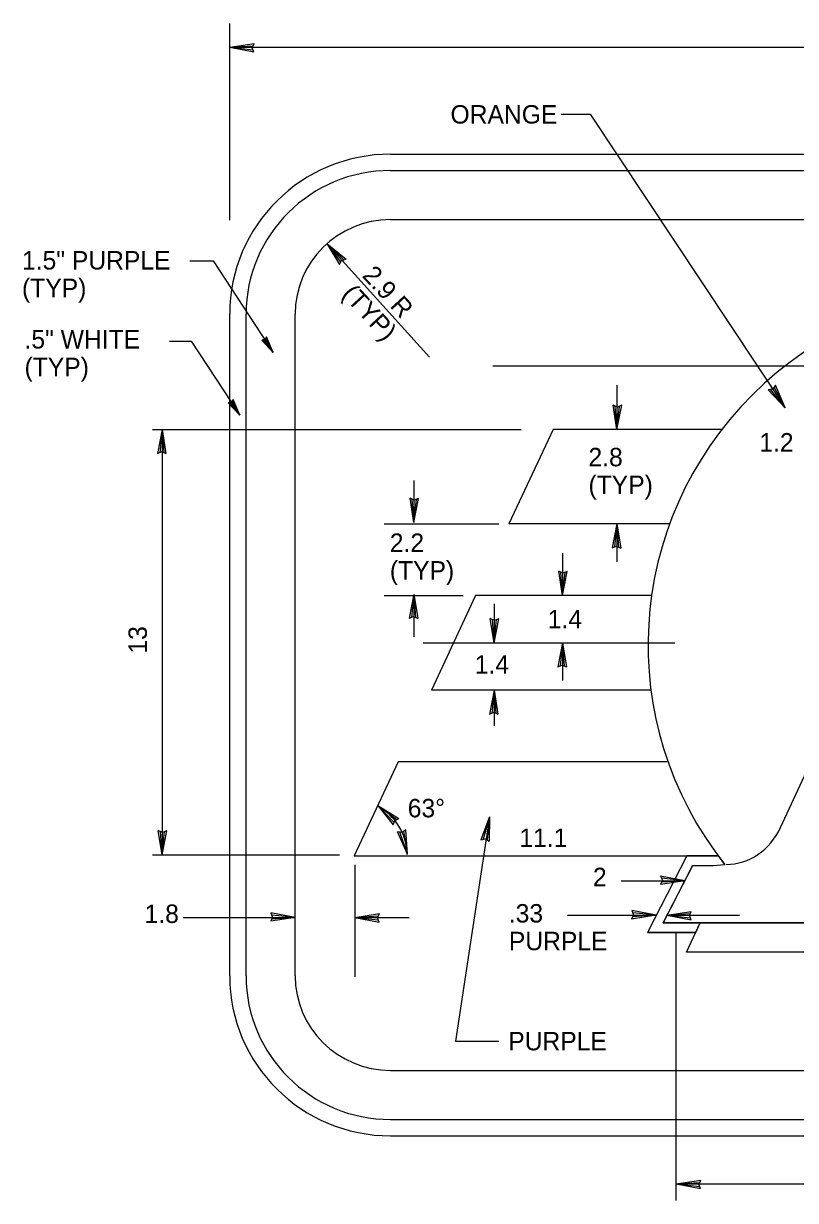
# Model space of a CAD drawing. Extents: x 10268197 to 10269179, y 2141503 to 2142677.
# Drawn here: x 10268665.92 to 10268695.42, y 2141995.31 to 2142040.27 of the extents above; entities that cross this region are included whole.
import ezdxf

# ---------------------------------------------------------------- set-up
doc = ezdxf.new("R2010")
doc.units = 0
for name, color, linetype in [('1', 7, 'Continuous'), ('Default', 7, 'Continuous'), ('TextMisc', 7, 'Continuous'), ('TextShtNo', 7, 'Continuous')]:
    doc.layers.add(name, color=color, linetype=linetype)

msp = doc.modelspace()

# ---------------------------------------------------------------- linework, layer by layer
at = {"layer": '1'}
for p, q in [((10268677.514, 2142031.863), (10268681.429, 2142027.519)), ((10268683.723, 2142009.967), (10268682.426, 2142001.389)), ((10268691.605, 2142005.546), (10268689.757, 2142005.546)), ((10268682.426, 2142001.389), (10268684.078, 2142001.389))]:
    msp.add_line(p, q, dxfattribs=at)
msp.add_ellipse((10268678.4, 2142008.499), major_axis=(-2.172, 0), ratio=0.990479, start_param=3.156002, end_param=4.207879, dxfattribs=at)
at = {"layer": 'Default'}
for p, q in [((10268673.796, 2142032.755), (10268673.796, 2142040.27)), ((10268673.796, 2142039.361), (10268674.728, 2142039.507)), ((10268673.796, 2142039.361), (10268674.689, 2142039.423)), ((10268673.796, 2142039.361), (10268722.546, 2142039.361)), ((10268673.796, 2142039.361), (10268674.723, 2142039.183)), ((10268673.796, 2142039.361), (10268674.687, 2142039.269)), ((10268674.654, 2142039.346), (10268674.728, 2142039.507)), ((10268674.723, 2142039.183), (10268674.654, 2142039.346)), ((10268686.467, 2142036.81), (10268687.571, 2142036.81)), ((10268687.571, 2142036.81), (10268695.023, 2142025.595)), ((10268679.942, 2142032.78), (10268716.4, 2142032.78)), ((10268677.514, 2142031.863), (10268678.246, 2142031.271)), ((10268677.514, 2142031.863), (10268677.997, 2142031.06)), ((10268677.514, 2142031.863), (10268678.038, 2142031.142)), ((10268677.514, 2142031.863), (10268678.155, 2142031.244)), ((10268672.274, 2142031.203), (10268673.161, 2142031.203)), ((10268673.161, 2142031.203), (10268675.463, 2142027.704)), ((10268677.997, 2142031.06), (10268678.074, 2142031.218)), ((10268678.074, 2142031.218), (10268678.246, 2142031.271)), ((10268676.296, 2142003.891), (10268676.296, 2142029.168)), ((10268671.5, 2142028.133), (10268672.326, 2142028.133)), ((10268672.326, 2142028.133), (10268674.183, 2142025.311)), ((10268675.14, 2142028.196), (10268675.019, 2142028.175)), ((10268675.463, 2142027.704), (10268675.019, 2142028.175)), ((10268675.463, 2142027.704), (10268675.082, 2142028.186)), ((10268675.207, 2142028.298), (10268675.14, 2142028.196)), ((10268675.463, 2142027.704), (10268675.171, 2142028.245)), ((10268675.463, 2142027.704), (10268675.207, 2142028.298)), ((10268683.847, 2142027.195), (10268700.38, 2142027.195)), ((10268694.99, 2142027.195), (10268699.515, 2142027.195)), ((10268688.595, 2142026.455), (10268688.595, 2142024.767)), ((10268694.551, 2142026.305), (10268694.375, 2142026.275)), ((10268695.023, 2142025.595), (10268694.375, 2142026.275)), ((10268695.023, 2142025.595), (10268694.467, 2142026.291)), ((10268694.649, 2142026.453), (10268694.551, 2142026.305)), ((10268695.023, 2142025.595), (10268694.597, 2142026.376)), ((10268695.023, 2142025.595), (10268694.649, 2142026.453)), ((10268673.86, 2142025.803), (10268673.739, 2142025.782)), ((10268673.926, 2142025.905), (10268673.86, 2142025.803)), ((10268674.183, 2142025.311), (10268673.891, 2142025.852)), ((10268674.183, 2142025.311), (10268673.926, 2142025.905)), ((10268674.183, 2142025.311), (10268673.739, 2142025.782)), ((10268674.183, 2142025.311), (10268673.802, 2142025.792)), ((10268688.595, 2142024.767), (10268688.447, 2142025.691)), ((10268688.61, 2142025.617), (10268688.447, 2142025.691)), ((10268688.595, 2142024.767), (10268688.532, 2142025.651)), ((10268688.595, 2142024.767), (10268688.775, 2142025.685)), ((10268688.595, 2142024.767), (10268688.688, 2142025.65)), ((10268688.775, 2142025.685), (10268688.61, 2142025.617)), ((10268670.851, 2142024.767), (10268684.931, 2142024.767)), ((10268671.213, 2142024.767), (10268671.034, 2142023.849)), ((10268671.213, 2142024.767), (10268671.12, 2142023.884)), ((10268671.213, 2142024.767), (10268671.213, 2142008.517)), ((10268671.213, 2142024.767), (10268671.36, 2142023.844)), ((10268671.213, 2142024.767), (10268671.275, 2142023.882)), ((10268686.152, 2142024.767), (10268684.468, 2142021.156)), ((10268692.605, 2142024.767), (10268686.152, 2142024.767)), ((10268671.034, 2142023.849), (10268671.198, 2142023.917)), ((10268671.198, 2142023.917), (10268671.36, 2142023.844)), ((10268694.844, 2142009.556), (10268701.361, 2142023.642)), ((10268680.836, 2142022.81), (10268680.836, 2142021.208)), ((10268680.836, 2142021.208), (10268680.688, 2142022.132)), ((10268680.851, 2142022.059), (10268680.688, 2142022.132)), ((10268680.836, 2142021.208), (10268680.773, 2142022.093)), ((10268680.836, 2142021.208), (10268681.015, 2142022.127)), ((10268680.836, 2142021.208), (10268680.929, 2142022.091)), ((10268681.015, 2142022.127), (10268680.851, 2142022.059)), ((10268679.699, 2142021.156), (10268684.082, 2142021.156)), ((10268690.608, 2142021.156), (10268684.468, 2142021.156)), ((10268688.595, 2142021.156), (10268688.415, 2142020.238)), ((10268688.595, 2142021.156), (10268688.502, 2142020.273)), ((10268688.595, 2142021.156), (10268688.595, 2142019.704)), ((10268688.595, 2142021.156), (10268688.743, 2142020.232)), ((10268688.595, 2142021.156), (10268688.658, 2142020.271)), ((10268686.518, 2142020.033), (10268686.518, 2142018.421)), ((10268688.415, 2142020.238), (10268688.58, 2142020.306)), ((10268688.58, 2142020.306), (10268688.743, 2142020.232)), ((10268686.518, 2142018.421), (10268686.37, 2142019.344)), ((10268686.532, 2142019.271), (10268686.37, 2142019.344)), ((10268686.518, 2142018.421), (10268686.455, 2142019.305)), ((10268686.518, 2142018.421), (10268686.697, 2142019.339)), ((10268686.518, 2142018.421), (10268686.611, 2142019.303)), ((10268686.697, 2142019.339), (10268686.532, 2142019.271)), ((10268679.699, 2142018.421), (10268682.713, 2142018.421)), ((10268680.836, 2142018.471), (10268680.656, 2142017.552)), ((10268680.836, 2142018.471), (10268680.743, 2142017.588)), ((10268680.836, 2142018.471), (10268680.836, 2142016.839)), ((10268680.836, 2142018.471), (10268680.984, 2142017.547)), ((10268680.836, 2142018.471), (10268680.899, 2142017.586)), ((10268683.193, 2142018.421), (10268681.509, 2142014.809)), ((10268689.919, 2142018.421), (10268683.193, 2142018.421)), ((10268683.9, 2142018.098), (10268683.9, 2142016.615)), ((10268680.656, 2142017.552), (10268680.821, 2142017.62)), ((10268680.821, 2142017.62), (10268680.984, 2142017.547)), ((10268683.9, 2142016.615), (10268683.752, 2142017.539)), ((10268683.915, 2142017.466), (10268683.752, 2142017.539)), ((10268683.9, 2142016.615), (10268683.837, 2142017.499)), ((10268683.9, 2142016.615), (10268684.079, 2142017.533)), ((10268683.9, 2142016.615), (10268683.993, 2142017.498)), ((10268684.079, 2142017.533), (10268683.915, 2142017.466)), ((10268681.187, 2142016.615), (10268690.809, 2142016.615)), ((10268686.518, 2142016.615), (10268686.338, 2142015.697)), ((10268686.518, 2142016.615), (10268686.425, 2142015.732)), ((10268686.518, 2142016.615), (10268686.518, 2142015.175)), ((10268686.518, 2142016.615), (10268686.665, 2142015.692)), ((10268686.518, 2142016.615), (10268686.581, 2142015.73)), ((10268686.338, 2142015.697), (10268686.503, 2142015.765)), ((10268686.503, 2142015.765), (10268686.665, 2142015.692)), ((10268689.897, 2142014.809), (10268681.509, 2142014.809)), ((10268683.9, 2142014.809), (10268683.72, 2142013.891)), ((10268683.9, 2142014.809), (10268683.807, 2142013.926)), ((10268683.9, 2142014.809), (10268683.9, 2142013.446)), ((10268683.9, 2142014.809), (10268684.048, 2142013.886)), ((10268683.9, 2142014.809), (10268683.963, 2142013.924)), ((10268683.72, 2142013.891), (10268683.885, 2142013.959)), ((10268683.885, 2142013.959), (10268684.048, 2142013.886)), ((10268680.232, 2142012.072), (10268678.556, 2142008.477)), ((10268690.513, 2142012.072), (10268680.232, 2142012.072)), ((10268679.463, 2142010.397), (10268680.264, 2142009.903)), ((10268679.463, 2142010.397), (10268680.046, 2142009.661)), ((10268679.463, 2142010.397), (10268680.075, 2142009.749)), ((10268679.463, 2142010.397), (10268680.179, 2142009.865)), ((10268680.046, 2142009.661), (10268680.102, 2142009.829)), ((10268680.102, 2142009.829), (10268680.264, 2142009.903)), ((10268683.723, 2142009.967), (10268683.393, 2142009.09)), ((10268683.723, 2142009.967), (10268683.485, 2142009.111)), ((10268683.723, 2142009.967), (10268683.637, 2142009.084)), ((10268683.723, 2142009.967), (10268683.716, 2142009.031)), ((10268671.213, 2142008.517), (10268671.066, 2142009.44)), ((10268671.227, 2142009.367), (10268671.066, 2142009.44)), ((10268671.213, 2142008.517), (10268671.15, 2142009.402)), ((10268671.213, 2142008.517), (10268671.392, 2142009.435)), ((10268671.213, 2142008.517), (10268671.306, 2142009.4)), ((10268671.392, 2142009.435), (10268671.227, 2142009.367)), ((10268680.588, 2142008.536), (10268680.207, 2142009.391)), ((10268680.383, 2142009.362), (10268680.207, 2142009.391)), ((10268680.588, 2142008.536), (10268680.3, 2142009.375)), ((10268680.525, 2142009.469), (10268680.383, 2142009.362)), ((10268680.588, 2142008.536), (10268680.45, 2142009.412)), ((10268680.588, 2142008.536), (10268680.525, 2142009.469)), ((10268683.393, 2142009.09), (10268683.567, 2142009.129)), ((10268683.567, 2142009.129), (10268683.716, 2142009.031)), ((10268670.851, 2142008.517), (10268677.993, 2142008.517)), ((10268678.556, 2142008.477), (10268692.436, 2142008.477)), ((10268691.262, 2142008.477), (10268689.757, 2142005.546)), ((10268691.262, 2142008.477), (10268692.471, 2142008.477)), ((10268678.583, 2142008.136), (10268678.583, 2142003.854)), ((10268691.488, 2142008.11), (10268690.361, 2142005.913)), ((10268691.489, 2142008.11), (10268692.267, 2142008.11)), ((10268692.267, 2142008.11), (10268692.721, 2142008.145)), ((10268688.756, 2142007.526), (10268691.189, 2142007.526)), ((10268690.33, 2142007.54), (10268690.256, 2142007.379)), ((10268691.189, 2142007.526), (10268690.256, 2142007.379)), ((10268691.189, 2142007.526), (10268690.262, 2142007.704)), ((10268690.262, 2142007.704), (10268690.33, 2142007.54)), ((10268691.189, 2142007.526), (10268690.296, 2142007.463)), ((10268691.189, 2142007.526), (10268690.297, 2142007.617)), ((10268672.019, 2142006.121), (10268676.296, 2142006.121)), ((10268675.437, 2142006.136), (10268675.363, 2142005.976)), ((10268676.296, 2142006.121), (10268675.363, 2142005.976)), ((10268676.296, 2142006.121), (10268675.369, 2142006.299)), ((10268675.369, 2142006.299), (10268675.437, 2142006.136)), ((10268676.296, 2142006.121), (10268675.403, 2142006.06)), ((10268676.296, 2142006.121), (10268675.404, 2142006.214)), ((10268678.583, 2142006.121), (10268679.515, 2142006.268)), ((10268678.583, 2142006.121), (10268679.475, 2142006.184)), ((10268678.583, 2142006.121), (10268680.648, 2142006.121)), ((10268678.583, 2142006.121), (10268679.51, 2142005.944)), ((10268678.583, 2142006.121), (10268679.474, 2142006.03)), ((10268679.442, 2142006.108), (10268679.515, 2142006.268)), ((10268679.51, 2142005.944), (10268679.442, 2142006.108)), ((10268686.705, 2142006.205), (10268690.088, 2142006.205)), ((10268689.229, 2142006.219), (10268689.155, 2142006.059)), ((10268690.088, 2142006.205), (10268689.155, 2142006.059)), ((10268690.088, 2142006.205), (10268689.161, 2142006.382)), ((10268689.161, 2142006.382), (10268689.229, 2142006.219)), ((10268690.088, 2142006.205), (10268689.195, 2142006.143)), ((10268690.088, 2142006.205), (10268689.197, 2142006.297)), ((10268690.502, 2142006.205), (10268691.435, 2142006.351)), ((10268690.502, 2142006.205), (10268691.396, 2142006.267)), ((10268690.502, 2142006.205), (10268693.284, 2142006.205)), ((10268690.502, 2142006.205), (10268691.429, 2142006.027)), ((10268690.502, 2142006.205), (10268691.394, 2142006.113)), ((10268691.361, 2142006.19), (10268691.435, 2142006.351)), ((10268691.429, 2142006.027), (10268691.361, 2142006.19)), ((10268690.361, 2142005.913), (10268691.956, 2142005.913)), ((10268690.863, 2141995.31), (10268690.863, 2142005.564)), ((10268691.254, 2142004.792), (10268691.776, 2142005.913)), ((10268708.18, 2142005.913), (10268691.776, 2142005.913)), ((10268709.192, 2142004.792), (10268691.254, 2142004.792)), ((10268679.942, 2142000.28), (10268716.4, 2142000.28)), ((10268690.863, 2141995.941), (10268691.795, 2141996.086)), ((10268690.863, 2141995.941), (10268691.756, 2141996.002)), ((10268690.863, 2141995.941), (10268708.18, 2141995.941)), ((10268690.863, 2141995.941), (10268691.79, 2141995.763)), ((10268690.863, 2141995.941), (10268691.754, 2141995.848)), ((10268691.721, 2141995.926), (10268691.795, 2141996.086)), ((10268691.79, 2141995.763), (10268691.721, 2141995.926))]:
    msp.add_line(p, q, dxfattribs=at)
for centre, major_axis, ratio, start_param, end_param in [((10268679.941, 2142029.168), (-3.646, 0), 0.990479, 4.712389, 6.283185), ((10268703.457, 2142016.529), (13.672, 0), 0.990479, 0.906904, 3.809231), ((10268692.764, 2142010.726), (0, 2.577), 0.905854, 3.141593, 4.241135), ((10268679.941, 2142003.89), (-3.646, 0), 0.990479, 0, 1.570796)]:
    msp.add_ellipse(centre, major_axis=major_axis, ratio=ratio, start_param=start_param, end_param=end_param, dxfattribs=at)
at = {"layer": 'TextMisc'}
for p, q in [((10268679.942, 2142035.28), (10268716.4, 2142035.28)), ((10268679.942, 2142034.655), (10268716.4, 2142034.655)), ((10268673.796, 2142003.891), (10268673.796, 2142029.168)), ((10268674.421, 2142003.891), (10268674.421, 2142029.168)), ((10268679.942, 2141998.405), (10268716.4, 2141998.405)), ((10268679.942, 2141997.78), (10268716.4, 2141997.78))]:
    msp.add_line(p, q, dxfattribs=at)
for centre, major_axis, ratio, start_param, end_param in [((10268679.941, 2142029.168), (-6.146, 0), 0.994352, 4.712389, 6.283185), ((10268679.941, 2142029.168), (-5.521, 0), 0.993713, 4.712389, 6.283185), ((10268679.941, 2142003.89), (-6.146, 0), 0.994352, 0, 1.570796), ((10268679.941, 2142003.89), (-5.521, 0), 0.993713, 0, 1.570796)]:
    msp.add_ellipse(centre, major_axis=major_axis, ratio=ratio, start_param=start_param, end_param=end_param, dxfattribs=at)
at = {"layer": 'TextShtNo'}
for p, q in [((10268691.254, 2142004.792), (10268691.776, 2142005.913)), ((10268691.776, 2142005.913), (10268708.18, 2142005.913)), ((10268709.192, 2142004.792), (10268691.254, 2142004.792))]:
    msp.add_line(p, q, dxfattribs=at)
msp.add_lwpolyline([(10268692.471, 2142008.477), (10268691.262, 2142008.477), (10268689.757, 2142005.546), (10268691.605, 2142005.546), (10268691.776, 2142005.913), (10268690.361, 2142005.913), (10268691.489, 2142008.11), (10268692.267, 2142008.11), (10268692.721, 2142008.145)], close=True, dxfattribs=at)

# ---------------------------------------------------------------- texts
at = {"layer": '1'}
for s, height, p in [('ORANGE', 0.7047, (10268682.234, 2142036.448)), ('1.5" PURPLE', 0.70474, (10268665.858, 2142030.873)), ('(TYP)', 0.7047, (10268665.858, 2142029.816)), ('.5" WHITE', 0.7047, (10268665.955, 2142027.855)), ('(TYP)', 0.7047, (10268665.955, 2142026.798)), ('1.2', 0.7047, (10268694.035, 2142023.92)), ('2.8', 0.7047, (10268687.506, 2142023.356)), ('(TYP)', 0.7047, (10268687.506, 2142022.299)), ('2.2', 0.7047, (10268679.914, 2142020.085)), ('(TYP)', 0.7047, (10268679.914, 2142019.028)), ('1.4', 0.7047, (10268685.951, 2142017.167)), ('1.4', 0.7047, (10268683.161, 2142015.436)), ('63°', 0.7047, (10268680.6, 2142009.946)), ('11.1', 0.7047, (10268684.865, 2142008.814)), ('2', 0.705, (10268687.677, 2142007.315)), ('1.8', 0.7047, (10268670.544, 2142005.911)), ('.33', 0.7047, (10268684.463, 2142005.927)), ('PURPLE', 0.7047, (10268684.463, 2142004.869)), ('PURPLE', 0.7047, (10268684.439, 2142001.046))]:
    msp.add_text(s, height=height, dxfattribs=at).set_placement(p)
for s, rotation, p in [('2.9 R', 312.7082, (10268678.827, 2142030.618)), ('(TYP)', 312.7082, (10268678.05, 2142029.901)), ('13', 90, (10268670.632, 2142016.201))]:
    msp.add_text(s, height=0.7047, rotation=rotation, dxfattribs=at).set_placement(p)

doc.saveas('drawing.dxf')
